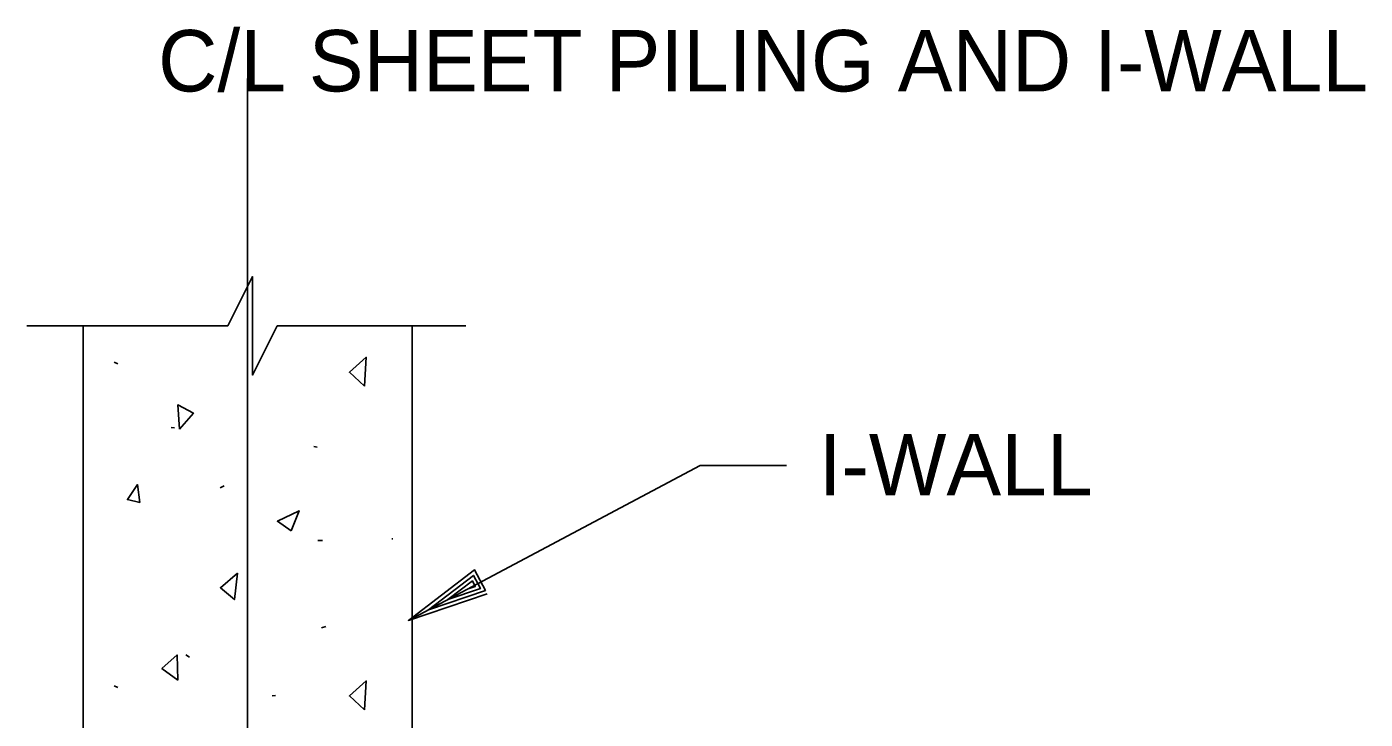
# Model space of a CAD drawing. Extents: x 22422.9 to 22498.9, y 22369.6 to 22415.
# Drawn here: x 22430.46 to 22434.526, y 22396.418 to 22398.522 of the extents above; entities that cross this region are included whole.
import ezdxf

# ---------------------------------------------------------------- set-up
doc = ezdxf.new("R2010")
doc.units = 0
for name, color, linetype in [('Level 1', 7, 'Continuous'), ('Level 2', 7, 'Continuous'), ('Level 4', 7, 'Continuous'), ('Level 44', 7, 'Continuous'), ('Level 7', 7, 'Continuous'), ('Level 8', 7, 'Continuous')]:
    doc.layers.add(name, color=color, linetype=linetype)

msp = doc.modelspace()

# ---------------------------------------------------------------- linework, layer by layer
at = {"layer": 'Level 1'}
for p, q in [((22431.1304, 22388.8739), (22431.1304, 22398.3655)), ((22430.4595, 22397.6134), (22431.0705, 22397.6134)), ((22431.2205, 22397.6134), (22431.7934, 22397.6134))]:
    msp.add_line(p, q, dxfattribs=at)
at = {"layer": 'Level 2'}
for points in [[(22432.7679, 22397.1889), (22432.5056, 22397.1889), (22431.619, 22396.7182)], [(22431.8587, 22396.7987), (22431.619, 22396.7182), (22431.8199, 22396.8717), (22431.853, 22396.8092), (22431.6803, 22396.7507), (22431.8167, 22396.8549), (22431.838, 22396.8149), (22431.7392, 22396.782), (22431.8135, 22396.8381), (22431.8223, 22396.8216), (22431.8004, 22396.8145)]]:
    msp.add_lwpolyline(points, dxfattribs=at)
at = {"layer": 'Level 44'}
for p, q in [((22430.7358, 22397.4976), (22430.7251, 22397.5026)), ((22430.9086, 22397.3033), (22430.8986, 22397.3041)), ((22431.3418, 22397.2448), (22431.3318, 22397.2466)), ((22431.0588, 22397.1271), (22431.0468, 22397.1211)), ((22431.3578, 22396.9611), (22431.3443, 22396.9611)), ((22431.5713, 22396.9658), (22431.5691, 22396.9658)), ((22431.3686, 22396.6993), (22431.3551, 22396.6956)), ((22430.9536, 22396.6068), (22430.9423, 22396.6136)), ((22430.7358, 22396.5138), (22430.7251, 22396.5188)), ((22431.2156, 22396.4898), (22431.2046, 22396.4888))]:
    msp.add_line(p, q, dxfattribs=at)
for points in [[(22431.4858, 22397.4296), (22431.4396, 22397.4723), (22431.4908, 22397.5181)], [(22430.9231, 22397.2998), (22430.9658, 22397.3478), (22430.9181, 22397.3733)], [(22430.8028, 22397.0763), (22430.7958, 22397.1311), (22430.7651, 22397.0853)], [(22431.2633, 22396.9903), (22431.2871, 22397.0516), (22431.2208, 22397.0193)], [(22431.0993, 22396.8621), (22431.0481, 22396.8173), (22431.0906, 22396.7816)], [(22430.9181, 22396.5361), (22430.8701, 22396.5723), (22430.9161, 22396.6131)], [(22431.4858, 22396.4458), (22431.4396, 22396.4886), (22431.4908, 22396.5343)]]:
    msp.add_lwpolyline(points, close=True, dxfattribs=at)
at = {"layer": 'Level 7'}
for p, q in [((22430.6304, 22395.7373), (22430.6304, 22397.6134)), ((22431.6304, 22395.7373), (22431.6304, 22397.6134))]:
    msp.add_line(p, q, dxfattribs=at)
at = {"layer": 'Level 8'}
for p, q in [((22431.619, 22396.7182), (22431.619, 22396.7182)), ((22431.6803, 22396.7507), (22431.6803, 22396.7507))]:
    msp.add_line(p, q, dxfattribs=at)
msp.add_lwpolyline([(22431.0705, 22397.6134), (22431.145, 22397.7634), (22431.145, 22397.4637), (22431.2205, 22397.6134)], dxfattribs=at)

# ---------------------------------------------------------------- texts
at = {"layer": 'Level 4'}
for s, height, p in [('C/L SHEET PILING AND I-WALL', 0.186667, (22430.8585, 22398.3259)), ('I-WALL', 0.18667, (22432.8654, 22397.098))]:
    msp.add_text(s, height=height, dxfattribs=at).set_placement(p)

doc.saveas('drawing.dxf')
